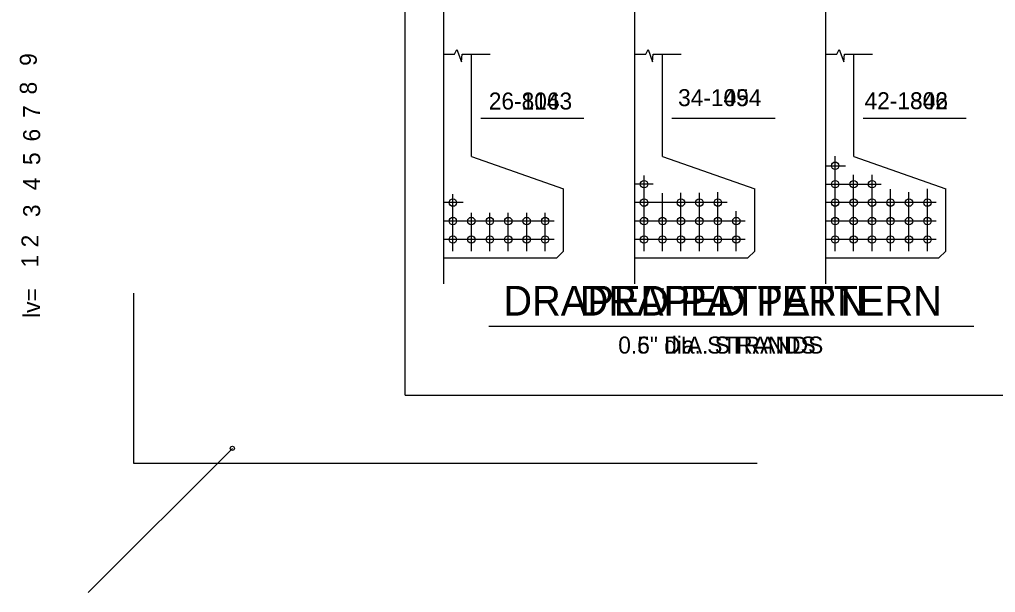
# Model space of a CAD drawing. Extents: x 1005.2 to 1101.8, y 1997.9 to 2073.7.
# Drawn here: x 1006.19 to 1025.34, y 2008.69 to 2019.94 of the extents above; entities that cross this region are included whole.
import ezdxf

# ---------------------------------------------------------------- set-up
doc = ezdxf.new("R2010")
doc.units = 0
for name, color, linetype in [('Level 1', 7, 'Continuous'), ('Level 2', 7, 'Continuous'), ('Level 3', 7, 'Continuous'), ('Level 4', 7, 'Continuous'), ('Level 49', 7, 'Continuous'), ('Level 5', 7, 'Continuous'), ('Level 6', 7, 'Continuous'), ('Level 7', 7, 'Continuous'), ('Level 8', 7, 'Continuous'), ('Level 9', 7, 'Continuous')]:
    doc.layers.add(name, color=color, linetype=linetype)

msp = doc.modelspace()

# ---------------------------------------------------------------- linework, layer by layer
at = {"layer": 'Level 1'}
for p, q in [((1013.763, 2012.562), (1013.763, 2068.561)), ((1008.43, 2014.568), (1008.43, 2011.228)), ((1013.763, 2012.562), (1097.431, 2012.562)), ((1008.43, 2011.228), (1020.664, 2011.228))]:
    msp.add_line(p, q, dxfattribs=at)
at = {"layer": 'Level 2'}
msp.add_line((1007.543, 2008.691), (1010.372, 2011.519), dxfattribs=at)
at = {"layer": 'Level 49'}
msp.add_circle((1010.371, 2011.519), 0.0405, dxfattribs=at)
at = {"layer": 'Level 8'}
for p, q in [((1014.516, 2014.747), (1014.516, 2034.639)), ((1018.266, 2014.747), (1018.266, 2034.639)), ((1022.016, 2014.747), (1022.016, 2034.639)), ((1014.516, 2019.258), (1014.729, 2019.258)), ((1014.729, 2019.258), (1014.776, 2019.347)), ((1014.776, 2019.347), (1014.865, 2019.104)), ((1014.865, 2019.104), (1014.878, 2019.258)), ((1014.878, 2019.258), (1015.427, 2019.258)), ((1015.06, 2017.248), (1015.06, 2019.258)), ((1018.266, 2019.258), (1018.479, 2019.258)), ((1018.479, 2019.258), (1018.526, 2019.347)), ((1018.526, 2019.347), (1018.615, 2019.104)), ((1018.615, 2019.104), (1018.628, 2019.258)), ((1018.628, 2019.258), (1019.177, 2019.258)), ((1018.81, 2017.248), (1018.81, 2019.258)), ((1022.016, 2019.258), (1022.229, 2019.258)), ((1022.229, 2019.258), (1022.276, 2019.347)), ((1022.276, 2019.347), (1022.365, 2019.104)), ((1022.365, 2019.104), (1022.378, 2019.258)), ((1022.378, 2019.258), (1022.927, 2019.258)), ((1022.56, 2017.248), (1022.56, 2019.258)), ((1015.244, 2017.998), (1017.269, 2017.998)), ((1018.994, 2017.998), (1021.019, 2017.998)), ((1022.744, 2017.998), (1024.769, 2017.998)), ((1015.06, 2017.248), (1016.869, 2016.614)), ((1018.81, 2017.248), (1020.619, 2016.614)), ((1022.197, 2015.392), (1022.197, 2017.256)), ((1022.56, 2017.248), (1024.369, 2016.614)), ((1022.016, 2017.066), (1022.397, 2017.066)), ((1018.447, 2015.392), (1018.447, 2016.874)), ((1022.559, 2015.392), (1022.559, 2016.887)), ((1022.921, 2015.392), (1022.921, 2016.887)), ((1016.869, 2015.392), (1016.869, 2016.614)), ((1018.629, 2016.704), (1018.266, 2016.704)), ((1020.619, 2015.392), (1020.619, 2016.614)), ((1022.016, 2016.704), (1023.101, 2016.704)), ((1023.283, 2015.392), (1023.283, 2016.603)), ((1024.007, 2015.392), (1024.007, 2016.614)), ((1024.369, 2015.392), (1024.369, 2016.614)), ((1014.697, 2015.392), (1014.697, 2016.506)), ((1018.809, 2015.392), (1018.809, 2016.528)), ((1019.171, 2015.392), (1019.171, 2016.532)), ((1019.533, 2015.392), (1019.533, 2016.536)), ((1019.895, 2015.392), (1019.895, 2016.55)), ((1023.645, 2015.392), (1023.645, 2016.55)), ((1014.896, 2016.342), (1014.516, 2016.342)), ((1020.081, 2016.342), (1018.266, 2016.342)), ((1024.181, 2016.342), (1022.016, 2016.342)), ((1015.059, 2015.392), (1015.059, 2016.139)), ((1015.421, 2015.392), (1015.421, 2016.139)), ((1015.783, 2015.392), (1015.783, 2016.139)), ((1016.145, 2015.392), (1016.145, 2016.139)), ((1016.507, 2015.392), (1016.507, 2016.139)), ((1020.257, 2015.392), (1020.257, 2016.177)), ((1016.681, 2015.98), (1014.516, 2015.98)), ((1020.431, 2015.98), (1018.266, 2015.98)), ((1024.181, 2015.98), (1022.016, 2015.98)), ((1016.681, 2015.618), (1014.516, 2015.618)), ((1020.431, 2015.618), (1018.266, 2015.618)), ((1024.181, 2015.618), (1022.016, 2015.618)), ((1014.516, 2015.256), (1016.733, 2015.256)), ((1016.733, 2015.256), (1016.869, 2015.392)), ((1018.266, 2015.256), (1020.483, 2015.256)), ((1020.483, 2015.256), (1020.619, 2015.392)), ((1022.016, 2015.256), (1024.233, 2015.256)), ((1024.233, 2015.256), (1024.369, 2015.392)), ((1020.318, 2014.462), (1020.318, 2014.661)), ((1020.318, 2014.462), (1020.318, 2014.661)), ((1020.318, 2014.462), (1020.318, 2014.606)), ((1016.899, 2013.919), (1024.917, 2013.919))]:
    msp.add_line(p, q, dxfattribs=at)
for centre in [(1022.197, 2017.066), (1018.447, 2016.704), (1022.197, 2016.704), (1022.921, 2016.704), (1014.697, 2016.342), (1018.447, 2016.342), (1019.171, 2016.342), (1019.533, 2016.342), (1019.895, 2016.342), (1022.197, 2016.342), (1022.559, 2016.342), (1022.921, 2016.342), (1023.283, 2016.342), (1023.645, 2016.342), (1024.007, 2016.342), (1014.697, 2015.98), (1015.059, 2015.98), (1015.421, 2015.98), (1015.783, 2015.98), (1016.145, 2015.98), (1016.507, 2015.98), (1018.447, 2015.98), (1018.809, 2015.98), (1019.171, 2015.98), (1019.533, 2015.98), (1019.895, 2015.98), (1020.257, 2015.98), (1022.197, 2015.98), (1022.559, 2015.98), (1022.921, 2015.98), (1023.283, 2015.98), (1023.645, 2015.98), (1024.007, 2015.98), (1014.697, 2015.618), (1015.059, 2015.618), (1015.421, 2015.618), (1015.783, 2015.618), (1016.145, 2015.618), (1016.507, 2015.618), (1018.447, 2015.618), (1018.809, 2015.618), (1019.171, 2015.618), (1019.533, 2015.618), (1019.895, 2015.618), (1020.257, 2015.618), (1022.197, 2015.618), (1022.559, 2015.618), (1022.921, 2015.618), (1023.283, 2015.618), (1023.645, 2015.618), (1024.007, 2015.618)]:
    msp.add_circle(centre, 0.073, dxfattribs=at)
at = {"layer": 'Level 9'}
for p, q in [((1014.516, 2014.747), (1014.516, 2034.639)), ((1018.266, 2014.747), (1018.266, 2034.639)), ((1022.016, 2014.747), (1022.016, 2034.639)), ((1014.516, 2019.258), (1014.729, 2019.258)), ((1014.729, 2019.258), (1014.776, 2019.347)), ((1014.776, 2019.347), (1014.865, 2019.104)), ((1014.865, 2019.104), (1014.878, 2019.258)), ((1014.878, 2019.258), (1015.427, 2019.258)), ((1015.06, 2017.248), (1015.06, 2019.258)), ((1018.266, 2019.258), (1018.479, 2019.258)), ((1018.479, 2019.258), (1018.526, 2019.347)), ((1018.526, 2019.347), (1018.615, 2019.104)), ((1018.615, 2019.104), (1018.628, 2019.258)), ((1018.628, 2019.258), (1019.177, 2019.258)), ((1018.81, 2017.248), (1018.81, 2019.258)), ((1022.016, 2019.258), (1022.229, 2019.258)), ((1022.229, 2019.258), (1022.276, 2019.347)), ((1022.276, 2019.347), (1022.365, 2019.104)), ((1022.365, 2019.104), (1022.378, 2019.258)), ((1022.378, 2019.258), (1022.927, 2019.258)), ((1022.56, 2017.248), (1022.56, 2019.258)), ((1015.244, 2017.998), (1017.269, 2017.998)), ((1018.994, 2017.998), (1021.019, 2017.998)), ((1022.744, 2017.998), (1024.769, 2017.998)), ((1015.06, 2017.248), (1016.869, 2016.614)), ((1018.81, 2017.248), (1020.619, 2016.614)), ((1022.56, 2017.248), (1024.369, 2016.614)), ((1018.447, 2015.392), (1018.447, 2016.874)), ((1022.197, 2015.392), (1022.197, 2016.887)), ((1022.559, 2015.392), (1022.559, 2016.887)), ((1022.921, 2015.392), (1022.921, 2016.887)), ((1016.869, 2015.392), (1016.869, 2016.614)), ((1018.629, 2016.704), (1018.266, 2016.704)), ((1020.619, 2015.392), (1020.619, 2016.614)), ((1022.016, 2016.704), (1023.101, 2016.704)), ((1023.283, 2015.392), (1023.283, 2016.603)), ((1024.007, 2015.392), (1024.007, 2016.614)), ((1024.369, 2015.392), (1024.369, 2016.614)), ((1014.697, 2015.392), (1014.697, 2016.506)), ((1018.809, 2015.392), (1018.809, 2016.528)), ((1019.171, 2015.392), (1019.171, 2016.532)), ((1019.533, 2015.392), (1019.533, 2016.536)), ((1019.895, 2015.392), (1019.895, 2016.55)), ((1023.645, 2015.392), (1023.645, 2016.55)), ((1014.896, 2016.342), (1014.516, 2016.342)), ((1020.081, 2016.342), (1018.266, 2016.342)), ((1024.181, 2016.342), (1022.016, 2016.342)), ((1015.059, 2015.392), (1015.059, 2016.139)), ((1015.421, 2015.392), (1015.421, 2016.139)), ((1015.783, 2015.392), (1015.783, 2016.139)), ((1016.145, 2015.392), (1016.145, 2016.139)), ((1016.507, 2015.392), (1016.507, 2016.139)), ((1020.257, 2015.392), (1020.257, 2016.177)), ((1016.681, 2015.98), (1014.516, 2015.98)), ((1020.431, 2015.98), (1018.266, 2015.98)), ((1024.181, 2015.98), (1022.016, 2015.98)), ((1016.681, 2015.618), (1014.516, 2015.618)), ((1020.431, 2015.618), (1018.266, 2015.618)), ((1024.181, 2015.618), (1022.016, 2015.618)), ((1014.516, 2015.256), (1016.733, 2015.256)), ((1016.733, 2015.256), (1016.869, 2015.392)), ((1018.266, 2015.256), (1020.483, 2015.256)), ((1020.483, 2015.256), (1020.619, 2015.392)), ((1022.016, 2015.256), (1024.233, 2015.256)), ((1024.233, 2015.256), (1024.369, 2015.392)), ((1018.822, 2014.462), (1018.822, 2014.661)), ((1018.822, 2014.462), (1018.822, 2014.661)), ((1018.822, 2014.462), (1018.822, 2014.606)), ((1015.403, 2013.919), (1023.422, 2013.919))]:
    msp.add_line(p, q, dxfattribs=at)
for centre in [(1018.447, 2016.704), (1022.197, 2016.704), (1022.559, 2016.704), (1022.921, 2016.704), (1014.697, 2016.342), (1018.447, 2016.342), (1019.171, 2016.342), (1019.533, 2016.342), (1019.895, 2016.342), (1022.197, 2016.342), (1022.559, 2016.342), (1022.921, 2016.342), (1023.283, 2016.342), (1023.645, 2016.342), (1024.007, 2016.342), (1014.697, 2015.98), (1015.059, 2015.98), (1015.421, 2015.98), (1015.783, 2015.98), (1016.145, 2015.98), (1016.507, 2015.98), (1018.447, 2015.98), (1018.809, 2015.98), (1019.171, 2015.98), (1019.533, 2015.98), (1019.895, 2015.98), (1020.257, 2015.98), (1022.197, 2015.98), (1022.559, 2015.98), (1022.921, 2015.98), (1023.283, 2015.98), (1023.645, 2015.98), (1024.007, 2015.98), (1014.697, 2015.618), (1015.059, 2015.618), (1015.421, 2015.618), (1015.783, 2015.618), (1016.145, 2015.618), (1016.507, 2015.618), (1018.447, 2015.618), (1018.809, 2015.618), (1019.171, 2015.618), (1019.533, 2015.618), (1019.895, 2015.618), (1020.257, 2015.618), (1022.197, 2015.618), (1022.559, 2015.618), (1022.921, 2015.618), (1023.283, 2015.618), (1023.645, 2015.618), (1024.007, 2015.618)]:
    msp.add_circle(centre, 0.073, dxfattribs=at)

# ---------------------------------------------------------------- texts
at = {"layer": 'Level 2'}
for s, height, p in [('2', 0.333, (1006.566, 2015.464)), ('1', 0.333, (1006.566, 2015.068)), ('lv=', 0.3333, (1006.599, 2014.079))]:
    msp.add_text(s, height=height, rotation=90, dxfattribs=at).set_placement(p)
at = {"layer": 'Level 3'}
msp.add_text('3', height=0.333, rotation=90, dxfattribs=at).set_placement((1006.599, 2016.058))
at = {"layer": 'Level 4'}
msp.add_text('4', height=0.333, rotation=90, dxfattribs=at).set_placement((1006.599, 2016.585))
at = {"layer": 'Level 5'}
msp.add_text('5', height=0.333, rotation=90, dxfattribs=at).set_placement((1006.599, 2017.08))
at = {"layer": 'Level 6'}
msp.add_text('6', height=0.333, rotation=90, dxfattribs=at).set_placement((1006.599, 2017.542))
at = {"layer": 'Level 7'}
msp.add_text('7', height=0.333, rotation=90, dxfattribs=at).set_placement((1006.599, 2018.003))
at = {"layer": 'Level 8'}
msp.add_text('8', height=0.333, rotation=90, dxfattribs=at).set_placement((1006.533, 2018.465))
for s, height, p in [('26-806', 0.3333, (1015.401, 2018.169)), ('34-1054', 0.3333, (1019.115, 2018.235)), ('42-1302', 0.3333, (1022.773, 2018.175)), ('DRAPED PATTERN', 0.58333, (1017.183, 2014.125)), ('0.5" DIA. STRANDS', 0.33333, (1017.941, 2013.38))]:
    msp.add_text(s, height=height, dxfattribs=at).set_placement(p)
at = {"layer": 'Level 9'}
msp.add_text('9', height=0.333, rotation=90, dxfattribs=at).set_placement((1006.533, 2019.026))
for s, height, p in [('26-1143', 0.3333, (1015.401, 2018.169)), ('34-1494', 0.3333, (1019.115, 2018.235)), ('42-1846', 0.3333, (1022.773, 2018.175)), ('DRAPED PATTERN', 0.58333, (1015.687, 2014.125)), ('0.6" dia. STRANDS', 0.33333, (1017.941, 2013.38))]:
    msp.add_text(s, height=height, dxfattribs=at).set_placement(p)

doc.saveas('drawing.dxf')
